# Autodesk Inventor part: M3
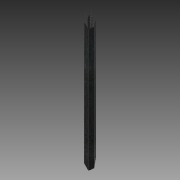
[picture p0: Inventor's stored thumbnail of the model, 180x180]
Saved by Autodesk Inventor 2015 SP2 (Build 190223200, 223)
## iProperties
Created: 2012-08
Part Number: M3
Material: Stahl
Document SubType Name: Modeling
Designer: rYan
Density: 7.85 g/cm^3
Mass: 3.36246 g
Surface Area: 5.74911 cm^2
Volume: 0.428339 cm^3
Appearance: Platte
Author: rYan
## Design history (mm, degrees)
derived "Abstandsbolzen Typ A.ipt"
feature "Volumenkörper1::Abstandsbolzen Typ A.ipt"
tag "Bezeichnung1"
node "Volumenkörper1"
other parameters: "SW" = 5.5, "d2" = 0, "d16" = 45 deg
